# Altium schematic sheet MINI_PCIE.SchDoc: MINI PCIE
size A3; Author: Daniela Catanzaro; CompanyName: Arduino srl; DocumentNumber: ASX00055; SheetNumber: 3; SheetTotal: 10; RevAuthor: Daniela Catanzaro
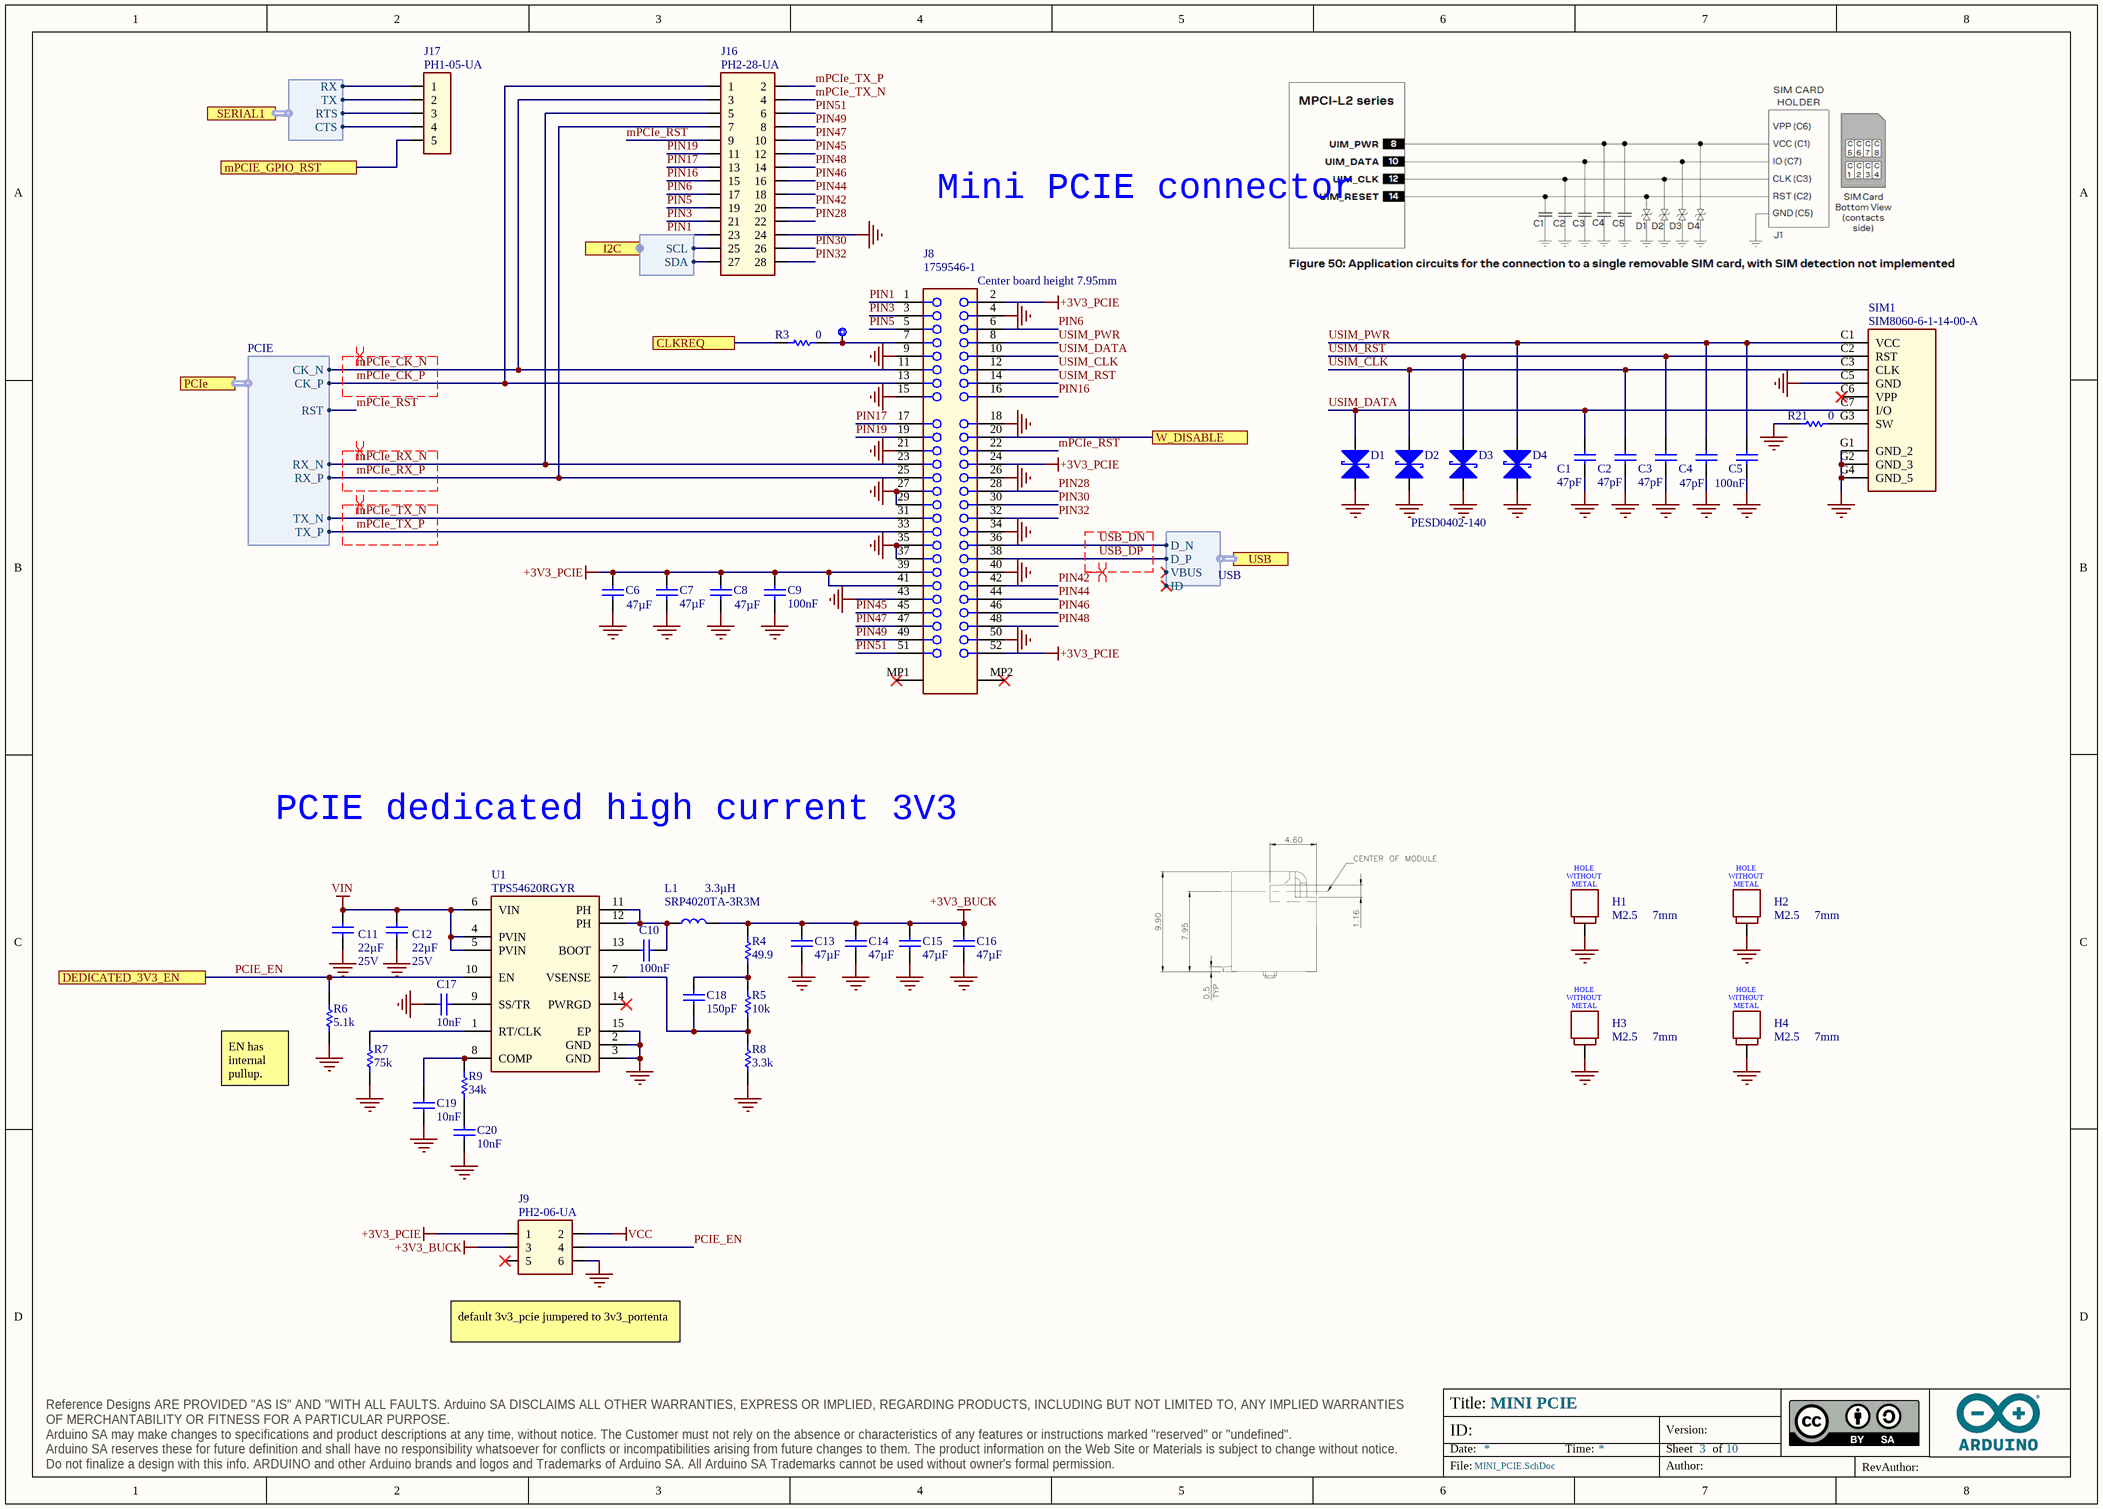
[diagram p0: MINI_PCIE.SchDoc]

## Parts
C1  value 47pF  [CAP-0402]  (hidden comment: CC0402JRNPO8BN470)
C2  value 47pF  [CAP-0402]  (hidden comment: CC0402JRNPO8BN470)
C3  value 47pF  [CAP-0402]  (hidden comment: CC0402JRNPO8BN470)
C4  value 47pF  [CAP-0402]  (hidden comment: CC0402JRNPO8BN470)
C5  value 100nF  [CAP-0603]  (hidden comment: 0603B104K500CT)
C6  value 47µF  [CAP-0603]  (hidden comment: GRM188R60J476ME15D)
C7  value 47µF  [CAP-0603]  (hidden comment: GRM188R60J476ME15D)
C8  value 47µF  [CAP-0603]  (hidden comment: GRM188R60J476ME15D)
C9  value 100nF  [CAP-0603]  (hidden comment: 0603B104K500CT)
C10  value 100nF  [CAP-0603]  (hidden comment: 0603B104K500CT)
C11  value 22µF  Voltage: 25V  [CAP-0805]  (hidden comment: CL21A226MAQNNNE)
C12  value 22µF  Voltage: 25V  [CAP-0805]  (hidden comment: CL21A226MAQNNNE)
C13  value 47µF  [CAP-0603]  (hidden comment: GRM188R60J476ME15D)
C14  value 47µF  [CAP-0603]  (hidden comment: GRM188R60J476ME15D)
C15  value 47µF  [CAP-0603]  (hidden comment: GRM188R60J476ME15D)
C16  value 47µF  [CAP-0603]  (hidden comment: GRM188R60J476ME15D)
C17  value 10nF  [CAP-0402]  (hidden comment: C1005B103K500NT)
C18  value 150pF  [CAP-0402]  (hidden comment: GRM1555C1H151FA01D)
C19  value 10nF  [CAP-0402]  (hidden comment: C1005B103K500NT)
C20  value 10nF  [CAP-0402]  (hidden comment: C1005B103K500NT)
D1  PESD0402-140  [0402]  (value not drawn)
D2  PESD0402-140  [0402]  (value not drawn)
D3  PESD0402-140  [0402]  (value not drawn)
D4  PESD0402-140  [0402]
H1  9774070151R NO METAL IN HOLE  [9774070151R_HOLE_NO_METAL]  (value not drawn)  (no BOM)
H2  9774070151R NO METAL IN HOLE  [9774070151R_HOLE_NO_METAL]  (value not drawn)  (no BOM)
H3  9774070151R NO METAL IN HOLE  [9774070151R_HOLE_NO_METAL]  (value not drawn)  (no BOM)
H4  9774070151R NO METAL IN HOLE  [9774070151R_HOLE_NO_METAL]  (value not drawn)  (no BOM)
J8  1759546-1  [1759546-1]
J9  PH2-06-UA  [2X03]
J16  PH2-28-UA  [PH2-28-UA]
J17  PH1-05-UA  [PH1-05-UA]
L1  SRP4020TA-3R3M  value 3.3µH  [SRP4020]
PCIE_CLKREQ1  Test point 1.00mm  [TP-1.00MM]  (value not drawn)  (no BOM)
R3  value 0  [RES-0603]  (hidden comment: CRCW06030000Z0EAC)
R4  value 49.9  [RES-0402]  (hidden comment: CRCW040249R9FKEDHP)
R5  value 10k  [RES-0402]  (hidden comment: CRCW040210K0FKED)
R6  value 5.1k  [RES-0402]  (hidden comment: RC0402FR-075K1L)
R7  value 75k  [RES-0402]  (hidden comment: CRCW040275K0FKED)
R8  value 3.3k  [RES-0402]  (hidden comment: RC0402FR-073K3L)
R9  value 34k  [RES-0402]  (hidden comment: RC0402FR-0734KL)
R21  value 0  [RES-0603]  (hidden comment: CRCW06030000Z0EAC)
SIM1  SIM8060-6-1-14-00-A  [SIM8060-6-0-14-00-A-Footprint-1]
U1  TPS54620RGYR  [RHL0014A_V]

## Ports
CLKREQ, DEDICATED_3V3_EN, I2C (harness I2C), mPCIE_GPIO_RST, PCIe (harness PCIE), SERIAL1 (harness UART), USB (harness USB), W_DISABLE

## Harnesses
USB: D_N, D_P, VBUS, ID
PCIE: CK_N, CK_P, RX_N, RX_P, TX_N, TX_P, RST
UART: CTS, RTS, TX, RX
I2C: SDA, SCL

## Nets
+3V3_BUCK: C13.2 C14.2 C15.2 C16.2 J9.3 L1.2 R4.2
+3V3_PCIE: C6.2 C7.2 C8.2 C9.1 J8.2 J8.24 J8.39 J8.41 J8.52 J9.1
GND: C1.1 C2.1 C3.1 C4.1 C5.1 C6.1 C7.1 C8.1 C9.2 C11.1 C12.1 C13.1 C14.1 C15.1 C16.1 C17.2 C19.1 C20.1 D1.A D2.A D3.A D4.A H1.1 H2.1 H3.1 H4.1 J8.4 J8.9 J8.15 J8.18 J8.21 J8.26 J8.27 J8.29 J8.34 J8.35 J8.37 J8.40 J8.43 J8.50 J9.6 J16.24 R6.1 R7.1 R8.1 R21.1 SIM1.C5(GND) SIM1.G1(GND_2) SIM1.G2(GND_3) SIM1.G4(GND_5) U1.2(GND) U1.3(GND) U1.15(EP)
VCC: J9.2
VIN: C11.2 C12.2 U1.4(PVIN) U1.5(PVIN) U1.6(VIN)
CLKREQ: R3.1 ; port CLKREQ
mPCIe_CK_N: J8.11 J16.3 ; port PCIe.CK_N
mPCIe_CK_P: J8.13 J16.1 ; port PCIe.CK_P
mPCIE_GPIO_RST: J17.5 ; port mPCIE_GPIO_RST
mPCIe_RST: J8.22 J16.9 ; port PCIe.RST
mPCIe_RX_N: J8.23 J16.5 ; port PCIe.RX_N
mPCIe_RX_P: J8.25 J16.7 ; port PCIe.RX_P
mPCIe_TX_N: J8.31 J16.4 ; port PCIe.TX_N
mPCIe_TX_P: J8.33 J16.2 ; port PCIe.TX_P
PCIE_EN: J9.4 R6.2 U1.10(EN) ; port DEDICATED_3V3_EN
PIN1: J8.1 J16.23
PIN3: J8.3 J16.21
PIN5: J8.5 J16.19
PIN6: J8.6 J16.17
PIN16: J8.16 J16.15
PIN17: J8.17 J16.13
PIN19: J8.19 J16.11
PIN28: J8.28 J16.22
PIN30: J8.30 J16.26
PIN32: J8.32 J16.28
PIN42: J8.42 J16.20
PIN44: J8.44 J16.18
PIN45: J8.45 J16.12
PIN46: J8.46 J16.16
PIN47: J8.47 J16.10
PIN48: J8.48 J16.14
PIN49: J8.49 J16.8
PIN51: J8.51 J16.6
USB_DN: J8.36 ; port USB.D_N
USB_DP: J8.38 ; port USB.D_P
USIM_CLK: C2.2 D2.C J8.12 SIM1.C3(CLK)
USIM_DATA: C1.2 D1.C J8.10 SIM1.C7(I/O)
USIM_PWR: C4.2 C5.2 D4.C J8.8 SIM1.C1(VCC)
USIM_RST: C3.2 D3.C J8.14 SIM1.C2(RST)
W_DISABLE: J8.20 ; port W_DISABLE
NetC10_1: C10.1 U1.13(BOOT)
NetC10_2: C10.2 L1.1 U1.11(PH) U1.12(PH)
NetC17_1: C17.1 U1.9(SS/TR)
NetC18_1: C18.1 R5.1 R8.2 U1.7(VSENSE)
NetC18_2: C18.2 R4.1 R5.2
NetC19_2: C19.2 R9.2 U1.8(COMP)
NetC20_2: C20.2 R9.1
NetJ8_7: J8.7 PCIE_CLKREQ1.X R3.2
NetJ16_25: J16.25 ; port I2C.SCL
NetJ16_27: J16.27 ; port I2C.SDA
NetJ17_1: J17.1 ; port SERIAL1.RX
NetJ17_2: J17.2 ; port SERIAL1.TX
NetJ17_3: J17.3 ; port SERIAL1.RTS
NetJ17_4: J17.4 ; port SERIAL1.CTS
NetR7_2: R7.2 U1.1(RT/CLK)
NetR21_2: R21.2 SIM1.G3(SW)

Not connected (* = marked no-connect by the designer): J8 MP1(53)* MP2(54)*; J9 5*; SIM1 C6(VPP)*; U1 14(PWRGD)*

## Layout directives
differential pair; differential pair class USB; net class DIFFERENTIAL: USB_DN, USB_DP
differential pair; differential pair class PCIE; net class DIFFERENTIAL: mPCIe_CK_N, mPCIe_CK_P, mPCIe_RX_N, mPCIe_RX_P, mPCIe_TX_N, mPCIe_TX_P

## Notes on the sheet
- Mini PCIE connector
- PCIE dedicated high current 3V3
- (near R6) EN has internal pullup.
- (near J9) default 3v3_pcie jumpered to 3v3_portenta

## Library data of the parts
C1-C4 = C0097-A.11: CAP CHIP 0402 47pF 5% 25V C0G; Manufacturer: Yageo; Code Arduino: C0097
C5 C9 C10 = C0043-A.14: CAP CHIP 0603 100nF 10% 50V X7R; Manufacturer: Walsin; Code Arduino: 0015
C6-C8 C13-C16 = C0098-A.12: CAP CHIP 0603 47uF 20% 6.3V X5R; Manufacturer: Murata; Code Arduino: C0098
C11 C12 = C0111-A.7: CAP CHIP 0805 22uF 20% 25V X5R; Manufacturer: Samsung Electro-Mechanics; Code Arduino: C0111
C17 C19 C20 = C0009-A.15: CAP CHIP 0402 10nF 10% 50V X7R; Manufacturer: Hottech; Code Arduino: 0165
C18 = C0074-A.12: CAP CHIP 0402 150pF 1% 50V C0G; Manufacturer: Murata; Code Arduino: C0074
D1-D4 = D0027-A.4: DIODE TVS SMD 0402 14V 40V; Manufacturer: Littelfuse Inc; Device Type: ESD protection; Direction: Bidirectional; Code Arduino: 2280
H1-H4 = S0041-A.4: RND STANDOFF M2.5X0.45 no paste no metalization in hole; Manufacturer: Wurth Elektronik; Code Arduino: S0014
J8 = J0186-A.8: CONN PCI EXP MINI FEMALE 52POS Center board heigth 7.95mm; Manufacturer: TE Connectivity; Number of Positions: 52; PCB Mounting Orientation: Vertical; Code Arduino: J0186; Stack Height: 9.95mm; High Temperature Housing: Yes; PCB Mount Retention: Without; Stackable: No; Pitch: 0.8mm; Connector Type: Receptacle; Row Spacing: 0.031inch
J9 = J0004-A.5: CONN Header Through Hole 6 position 0.100" (2.54mm); Manufacturer: Adam Tech; Code Arduino: 0114
J16 = J0434-A.3: CONN. HEADER TH 2.54mm VERT. MALE 2x14POS; Manufacturer: Adam Tech; Code Arduino: J0434
J17 = J0390-A.5: CONN. HEADER TH 2.54mm VERT. MALE 1x5 POS; Manufacturer: Adam Tech; Code Arduino: J0390
L1 = I0049-A.6: IND FIXED SMD 3.3UH 3.5A 76 mOHM; Manufacturer: Bourns; DC Resistance (DCR): 76mR; Tolerance: 20%; Test Frequency: 100kHz; Current: 4A; Code Arduino: I0049
PCIE_CLKREQ1 = UT0013-A.6: Manufacturer: This is not a component
R3 = R0096-A.22: RES CHIP 0603 0R 1/10W; Manufacturer: Vishay; Code Arduino: 0233; Tolerance: 0%; Power: 100mW; Temperature coefficient: 0ppm
R4 = R0046-A.26: RES CHIP 0402 49R9 1% 1/16W; Manufacturer: Vishay; Power: 62.5mW; Temperature coefficient: 200ppm; Code Arduino: A5282
R5 = R0003-A.24: RES CHIP 0402 10k 1% 1/16W; Manufacturer: Vishay; Power: 62.5mW; Code Arduino: 0136; Temperature coefficient: 100ppm
R6 = R0210-A.19: RES CHIP 0402 5k1 1% 1/16W; Manufacturer: YAGEO; Code Arduino: R0210; Power: 62.5mW; Temperature coefficient: 100ppm
R7 = R0037-A.26: RES CHIP 0402 75k 1% 1/16W; Manufacturer: YAGEO; Code Arduino: A5480; Power: 62.5mW; Temperature coefficient: 100ppm
R8 = R0020-A.24: RES CHIP 0402 3k3 1% 1/16W; Manufacturer: YAGEO; Code Arduino: 2232; Power: 62.5mW; Temperature coefficient: 200ppm
R9 = R0172-A.26: RES CHIP 0402 34k 1% 1/16W; Manufacturer: YAGEO; Power: 62.5mW; Code Arduino: R0172; Temperature coefficient: 200ppm
R21 = R0096-A.22: RES CHIP 0603 0R 1/10W; Manufacturer: Vishay; Power: 100mW; Code Arduino: 0233; Temperature coefficient: 0ppm; Tolerance: 0%
SIM1 = J0300-A.1: CONN SIM NANO HINGED WITH SWITCH, 6P, 1.40MM PROF; Manufacturer: GCT; Code Arduino: J0300
U1 = U0092-A.9: IC REG BUCK ADJ 6A SYNC 14VQFN; Manufacturer: Texas Instruments; Code Arduino: U0092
